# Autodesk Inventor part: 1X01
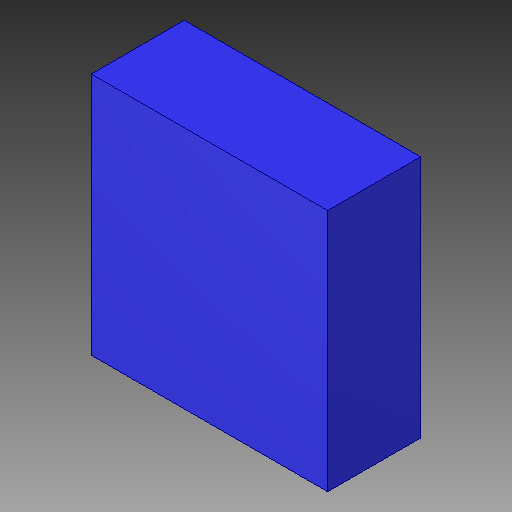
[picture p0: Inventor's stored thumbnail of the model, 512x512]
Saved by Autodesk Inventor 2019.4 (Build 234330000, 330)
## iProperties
Created: 2019-11
Part Number: 1X01
Material: Generic
Document SubType Name: Modeling
Designer: Willist
Density: 1 g/cm^3
Appearance: 1X01, 1X01
Author: Willist
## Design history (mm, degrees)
sketch "1X01, 1X01_39"
  geometry: L1 (-1.27, 1.346)-(1.27, 1.346); L2 (1.27, 1.346)-(1.27, -1.27); L3 (1.27, -1.27)-(-1.27, -1.27); L4 (-1.27, -1.27)-(-1.27, 1.346)
  constraints: 8 end point
extrude "Extrusion1" join sketch "1X01, 1X01_39" distance "d0" = 1; taper "d1" = 0 deg
body "Solid1"
